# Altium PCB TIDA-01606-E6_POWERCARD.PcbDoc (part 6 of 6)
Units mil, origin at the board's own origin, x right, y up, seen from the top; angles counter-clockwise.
Board outline 13779.53 x 7874.02 mil, 4 copper layers (Top Layer, Gnd Layer, Pwr Layer, Bottom Layer), stack 94.4 mil thick; 550 components, 292 nets, 1594 pads, 572 vias.
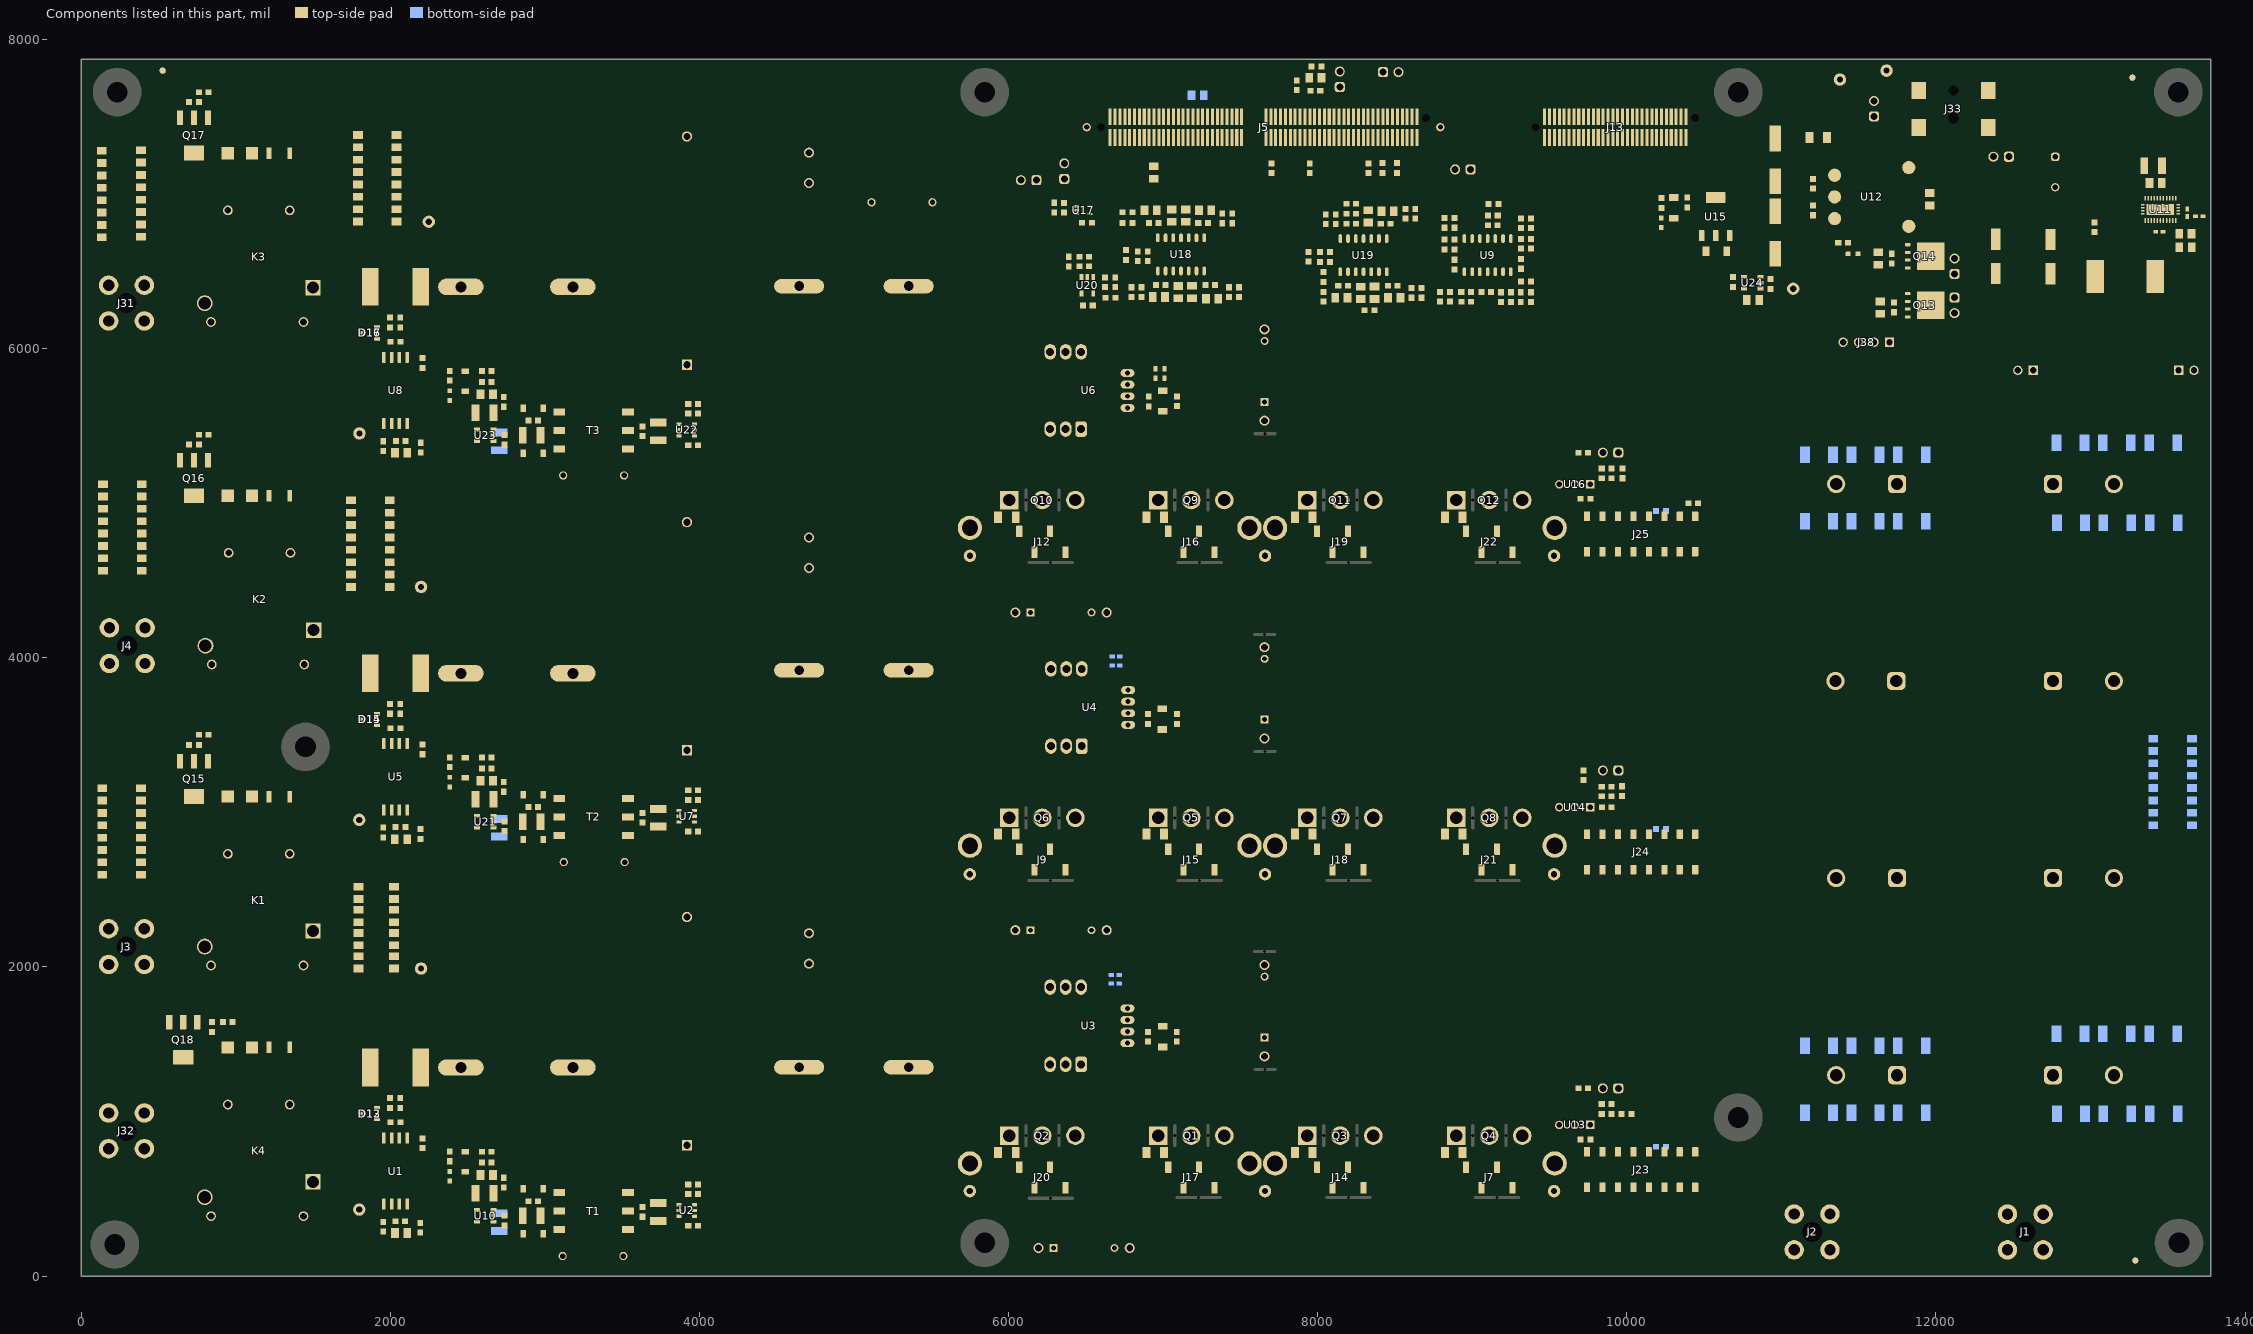
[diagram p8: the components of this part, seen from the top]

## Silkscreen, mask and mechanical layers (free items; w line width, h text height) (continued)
M4 3D STEP Bottom:
  lines w10: 6004.7,908.93 6004.7,2964.99 6004.7,5021.06 ; 6169.7,638.93 6219.7,688.93 6219.7,908.93 ; 6169.7,2694.99 6219.7,2744.99 6219.7,2964.99 ; 6169.7,4751.06 6219.7,4801.06 6219.7,5021.06 ; 6369.7,638.93 7033.48,638.93 ; 6369.7,2694.99 7033.48,2694.99 ; 6369.7,4751.06 7033.48,4751.06 ; 6434.7,908.93 6968.48,908.93 ; 6434.7,2964.99 6968.48,2964.99 ; 6434.7,5021.06 6968.48,5021.06 ; 7133.48,638.93 7183.48,688.93 7183.48,908.93 ; 7133.48,2694.99 7183.48,2744.99 7183.48,2964.99 ; 7133.48,4751.06 7183.48,4801.06 7183.48,5021.06 ; 7333.48,638.93 7997.26,638.93 ; 7333.48,2694.99 7997.26,2694.99 ; 7333.48,4751.06 7997.26,4751.06 ; 7398.48,908.93 7932.26,908.93 ; 7398.48,2964.99 7932.26,2964.99 ; 7398.48,5021.06 7932.26,5021.06 ; 8097.26,638.93 8147.26,688.93 8147.26,908.93 ; 8097.26,2694.99 8147.26,2744.99 8147.26,2964.99 ; 8097.26,4751.06 8147.26,4801.06 8147.26,5021.06 ; 8297.26,638.93 8961.04,638.93 ; 8297.26,2694.99 8961.04,2694.99 ; 8297.26,4751.06 8961.04,4751.06 ; 8362.26,908.93 8896.04,908.93 ; 8362.26,2964.99 8896.04,2964.99 ; 8362.26,5021.06 8896.04,5021.06 ; 9061.04,638.93 9111.04,688.93 9111.04,908.93 ; 9061.04,2694.99 9111.04,2744.99 9111.04,2964.99 ; 9061.04,4751.06 9111.04,4801.06 9111.04,5021.06 ; 9261.04,638.93 9742.93,638.93 ; 9261.04,2694.99 9742.93,2694.99 ; 9261.04,4751.06 9742.93,4751.06
  text ".Layer_Name" at -13.55,-858.49 h60
M5 Assembly Top:
  circle w10: c13573.69,5858.85 r7.25
  circle w10: c12623,5855.85 r7.25
  circle w10: c11701,6036.85 r7.25
  circle w10: c8421,7783.85 r7.25
  circle w10: c6181,7083.85 r7.25
  circle w10: c6548,6480.85 r7.25
  circle w10: c9742.93,4884.85 r7.25
  circle w10: c8960,4782.85 r7.25
  circle w10: c7999,4780.85 r7.25
  circle w10: c7035,4784.85 r7.25
  circle w10: c6071,4781.85 r7.25
  circle w10: c9742.93,2825.85 r7.25
  circle w10: c8964,2727.85 r7.25
  circle w10: c7998,2725.85 r7.25
  circle w10: c7036,2723.85 r7.25
  circle w10: c6071,2723.85 r7.25
  circle w10: c9742,768.85 r7.25
  circle w10: c8961,670.85 r7.25
  circle w10: c7997,669.85 r7.25
  circle w10: c7035,670.85 r7.25
  circle w10: c6071,665.85 r7.25
  circle w10: c1931,6063.85 r7.25
  circle w10: c1930,3565.29 r7.25
  circle w10: c1930,1014.6 r7.25
  circle w10: c6419,6922 r9.22
  circle w10: c6363,7098 r9.22
  circle w10: c8969,7187 r9.22
  circle w10: c10484,6815 r9.22
  circle w10: c11330,7113 r9.22
  circle w10: c12469,7240 r9.22
  circle w10: c12338,7669 r9.22
  circle w10: c9836,5332 r9.22
  circle w10: c6472,5498 r9.22
  circle w10: c6474,3445 r9.22
  circle w10: c9835,3271 r9.22
  circle w10: c6471,1388 r9.22
  circle w10: c9843,1217 r9.22
  circle w10: c8144,7689 r9.85
  circle w10: c2687,353 r7
  circle w10: c2689,2901.6 r7
  circle w10: c2688,5404 r7
  circle w10: c822,7420 r13.15
  circle w10: c816,5212 r7
  circle w10: c819,3264 r11.18
  circle w10: c750,1579 r10.05
  lines w10: -882.55,-930.17 5717.45,-930.17 ; -882.55,-726.83 5719.45,-726.83 ; -882.55,-523.5 -882.55,-1133.5 3122.45,-1133.5 5719.45,-1133.5 5719.45,-523.5 -882.05,-523.5 -882.05,-1133.5 693.45,-1133.5 ; 1582.45,-1133.5 1582.45,-523.5 ; 2849.45,-726.83 2849.45,-523.5 ; 3689.45,-726.83 3689.45,-523.5 ; 4311.45,-1140 4311.45,-937.17
  text "2" at 6643,7482 h72.83
  text "120" at 8631,7481 h72.83
  text "122" at 9421,7480 h72.83
  text "180" at 10368,7474 h72.83
  text "1" at 6642,7265 h72.83
  text "119" at 8630,7241 h72.83
  text "121" at 9411,7238 h72.83
  text "179" at 10372,7234 h72.83
  text "COMPONENTS MARKED 'DNP' SHOULD NOT BE POPULATED." at 562.95,-318.5 h25
  text "ASSEMBLY VARIANT:" at 562.45,-434 h25
  text ".VariantName" at 1598.45,-434 h25
  text "PCB VIEWED FROM TOP SIDE" at -819.05,-655.67 h25
  text "BOARD #:" at 1657.45,-655.67 h25
  text ".PRJ_Number" at 2202.95,-655.67 h25
  text "REV:" at 3047.45,-655.67 h25
  text ".PCB_Rev" at 3338.95,-655.67 h25
  text "SVN REV:" at 3885.45,-655.67 h25
  text ".VersionControl_RevNumber" at 4391.45,-655.67 h25
  text "LAYER NAME =" at -819.05,-858.49 h25
  text "'.Layer_Name'" at -471,-859 h25
  text "TID #:" at 1657.45,-859 h25
  text ".TID" at 2202.95,-859 h25
  text "PLOT NAME =" at -819.05,-1064.34 h25
  text ".plot_File_Name" at -13.55,-1064.34 h25
  text "GENERATED    :" at 1659.45,-1064.34 h25
  text ".Print_Date" at 2528.95,-1064.34 h25
  text ".Print_Time" at 3257.95,-1064.34 h25
  text "TEXAS INSTRUMENTS" at 4522.45,-1064.34 h25
M6 Assembly Bottom:
  circle w10: c1930,1090 r8.46
  circle w10: c1930,3639.4 r8.46
  circle w10: c1930,6140 r8.46
  circle w10: c6010,5060 r28.28
  circle w10: c6970,5069.84 r28.28
  circle w10: c7930,5069.84 r28.28
  circle w10: c8900,5069.84 r28.28
  circle w10: c6000,3010 r28.28
  circle w10: c6970,3010 r28.28
  circle w10: c7930,3000 r28.28
  circle w10: c8900,3020 r28.28
  circle w10: c8890,950.61 r28.28
  circle w10: c7940,960 r28.28
  circle w10: c6970,950 r28.28
  circle w10: c6010,950 r28.28
  circle w10: c9731,5123 r6.08
  circle w10: c9735,3028 r6.08
  circle w10: c9735,974 r6.08
  lines w10: -883.05,-727.33 5718.95,-727.33 ; -881.05,-930.67 5718.95,-930.67 ; 524.95,-1140.5 524.95,-937.67 ; 1146.95,-727.33 1146.95,-524 ; 1986.95,-727.33 1986.95,-524 ; 3253.95,-1134 3253.95,-524 ; 4142.95,-1134 5718.45,-1134 5718.45,-524 -883.05,-524 -883.05,-1134 1713.95,-1134 5718.95,-1134 5718.95,-524
  text "U14" at 9685,3023 h25
  text "COMPONENTS MARKED 'DNP' SHOULD NOT BE POPULATED." at 5511.45,-318 h25
  text ".VariantName" at 4467.45,-434 h25
  text "ASSEMBLY VARIANT:" at 5506.45,-434 h25
  text ".VersionControl_RevNumber" at 444.95,-656.17 h25
  text "SVN REV:" at 950.95,-656.17 h25
  text ".PCB_Rev" at 1497.45,-656.17 h25
  text "REV:" at 1788.95,-656.17 h25
  text ".PRJ_Number" at 2633.45,-656.17 h25
  text "BOARD #:" at 3178.95,-656.17 h25
  text "PCB VIEWED FROM BOTTOM SIDE" at 5655.45,-656.17 h25
  text "'.Layer_Name'" at 5339,-832 h30
  text "LAYER NAME =" at 5665.95,-832.49 h25
  text ".TID" at 2633.45,-859.5 h25
  text "TID #:" at 3178.95,-859.5 h25
  text "TEXAS INSTRUMENTS" at 313.95,-1064.84 h25
  text ".Print_Time" at 1578.45,-1064.84 h25
  text ".Print_Date" at 2307.45,-1064.84 h25
  text "GENERATED    :" at 3176.95,-1064.84 h25
  text ".plot_File_Name" at 4849.95,-1064.84 h25
  text "PLOT NAME =" at 5655.45,-1064.84 h25
M9 Title Sheet:
  drawing of 69 lines, arcs and shapes, not listed
  text "1" at 149.29,15036.5 h70
  text "2" at 2644.95,15036.5 h70
  text "3" at 5134.29,15036.5 h70
  text "4" at 7640.96,15036.5 h70
  text "5" at 16764.95,15036.5 h70
  text "6" at 19269.95,15036.5 h70
  text "A" at -1007.05,6893.5 h70
  text "A" at 20417.95,6893.5 h70
  text "B" at -1007.05,4513.5 h70
  text "B" at 20417.95,4513.5 h70
  text "C" at -1007.05,2138.5 h70
  text "C" at 20417.95,2138.5 h70
  text "PROJECT TITLE:" at 17377.95,277.5 h45
  text ".PRJ_Title" at 17427.95,144.17 h70
  text "DESIGNED FOR:" at 17377.95,-23.5 h45
  text ".PRJ_Customer" at 17427.95,-163.5 h70
  text "D" at -1007.05,-231.5 h70
  text "D" at 20417.95,-231.5 h70
  text "FILE NAME:" at 17377.95,-323.5 h45
  text ".PCB_File_Name_No_Path" at 17427.95,-443.5 h70
  text "Texas Instruments (TI) and/or its licensors do not warrant the accuracy or completeness of this specification" at 5783.45,-605.34 h45
  text "ENGINEER:" at 17377.95,-613.5 h45
  text "LAYOUT BY:" at 18882.95,-613.5 h45
  text "or any information contained therein. TI and/or its licensors do not warrant that this design will meet" at 5738.46,-718 h45
  text ".PRJ_Engineer" at 17427.95,-768.49 h70
  text ".PCB_Layout" at 18933.45,-768.49 h70
  text "the specifications, will be suitable for your application or fit for any particular purpose, or will operate in" at 5738.46,-830.67 h45
  text "ALTIUM DESIGNER VERSION:" at 18882.95,-923.5 h45
  text "an implementation. TI and/or its licensors do not warrant that the design is production worthy. You should" at 5738.46,-943.33 h45
  text "completely validate and test your design implementation to confirm the system functionality for your application." at 5783.45,-1056 h45
  text ".print_Scale" at 17427.95,-1056.83 h70
  text ".Application_BuildNumber" at 18933.45,-1056.83 h70
  text "1" at 149.29,-1263.5 h70
  text "2" at 2644.95,-1263.5 h70
  text "3" at 5134.29,-1263.5 h70
  text "4" at 7640.96,-1263.5 h70
  text "5" at 16764.95,-1263.5 h70
  text "6" at 19269.95,-1263.5 h70
M10 Fab Notes:
  drawing of 228 lines, arcs and shapes, not listed
  text "DESIGN INFORMATION" at 18417.37,6834.03 h60
  text "(REFER ALSO ARRAY/PANEL PROFILING INFORMATION)" at 18055.81,6672.32 h60
  text "BOARD SIZE" at 17369.81,6668.03 h60
  text "350MM" at 17832.13,6540.21 h60
  text "X" at 18337.81,6540.21 h60
  text "200MM" at 18569.13,6540.21 h60
  text "Number of Layers :" at 17772.81,6343.03 h60
  text "4" at 18867.62,6333.04 h60
  text "10" at 18846.45,6206 h60
  text "MIN. TRACK WIDTH:" at 17772.81,6204.03 h60
  text "MIL" at 19023.81,6204.03 h60
  text "MIL" at 19024.45,6087 h60
  text "7.87" at 18789,6079 h60
  text "MIN. CLEARANCE:" at 17772.81,6072.03 h60
  text "12" at 18856,5959 h60
  text "MIL" at 19027.45,5953 h60
  text "MIN. VIA DRILL SIZE:" at 17772.81,5940.03 h60
  text "MINIMUM ANNULAR RING" at 17443.58,5794.04 h60
  text "EXTERNAL" at 19175.81,5794.04 h60
  text "5.90 MIL" at 18487.45,5792 h60
  text "PER" at 17643.58,5676.04 h60
  text "IPC-D-275 CLASS 2 LEVEL C" at 17863.58,5676.03 h60
  text "MIL, HOLES" at 19351.81,5563.75 h60
  text "+/-" at 18959.35,5563.04 h60
  text "+/-" at 19813.35,5563.04 h60
  text "REGISTRATION TOLERANCES:" at 17443.58,5558.03 h60
  text "METAL" at 18643.35,5558.03 h60
  text "5" at 19219.55,5558.04 h60
  text "3" at 20052.55,5558.04 h60
  text "MIL" at 20168.81,5558.03 h60
  text "MATERIAL:" at 17368.81,5348.58 h60
  text "FR-4 High Tg" at 18355.25,5208.24 h60
  text "FR-408" at 17789.81,5199.67 h60
  text "X" at 18196.35,5200.03 h60
  text "OTHER" at 19277.81,5199.67 h60
  text "OTHER" at 19509.81,5039.67 h60
  text "94.48 MIL (2.4mm) +/-10%" at 18109.91,5036.96 h60
  text "THICKNESS:" at 17443.58,5032.67 h60
  text "X" at 17981.75,5032.67 h60
  text "TOLERANCE:" at 17443.58,4874.67 h60
  text "X" at 18282.88,4874.67 h60
  text "ANSI IPC-6012 TYPE 3 CLASS 2" at 18469.82,4874.67 h60
  text "OTHER +/-" at 18469.81,4718.67 h60
  text "BOW & TWIST:" at 17443.58,4561.67 h60
  text "X" at 18282.88,4561.67 h60
  text "ANSI IPC-6012 TYPE 3 CLASS 2" at 18469.82,4561.67 h60
  text "OTHER +/-" at 18469.81,4403.17 h60
  text "COPPER THICKNESS (FINISHED):" at 17368.81,4267.67 h60
  text "X" at 19618.35,4119.03 h60
  text "1.4MIL (1oz)" at 18248.81,4114.96 h60
  text "2MIL (1.4oz)" at 19015.81,4114.96 h60
  text "2.8MIL (2oz)" at 19742.81,4114.96 h60
  text "OUTER:" at 17725.81,4110.67 h60
  text "1.4MIL (1oz)" at 18248.81,3957.96 h60
  text "2.8MIL (2oz)" at 19015.81,3957.96 h60
  text "N/A" at 19742.35,3958.32 h60
  text "X" at 18888.35,3956.03 h60
  text "INNER SIGNAL:" at 17436.73,3953.67 h60
  text "DRILLING:" at 17368.81,3814.67 h60
  text "REFERENCE:" at 17443.58,3697.67 h60
  text "X" at 18091.81,3697.67 h60
  text "AS SHOWN" at 18278.81,3697.67 h60
  text "X" at 18992.81,3697.67 h60
  text "NC_DRILL FILES" at 19129.81,3697.67 h60
  text "PTH MIN COPPER THICKNESS:" at 17443.58,3539.67 h60
  text "X" at 18793.81,3539.67 h60
  text "1MIL" at 18930.81,3539.67 h60
  text "OTHER" at 19427.81,3539.67 h60
  text "BOARD FINISH:" at 17368.81,3380.67 h60
  text "SILKSCREEN:" at 17524.03,3262.67 h60
  text "X" at 18472.81,3262.67 h60
  text "TOP" at 18598.81,3262.67 h60
  text "BOTTOM" at 19109.81,3262.67 h60
  text "X" at 18990.35,3259.03 h60
  text "SILKSCREEN COLOR:" at 17524.03,3095.67 h60
  text "X" at 18471.77,3095.67 h60
  text "WHITE" at 18598.81,3095.67 h60
  text "OTHER" at 19109.81,3095.67 h60
  text "SOLDER RESIST COLOR:" at 17524.03,2925.67 h60
  text "X" at 18091.77,2766.48 h60
  text "GREEN" at 18218.81,2766.48 h60
  text "BLUE" at 18809.81,2766.48 h60
  text "OTHER" at 19347.81,2766.48 h60
  text "IMMERSION GOLD (ENIG)" at 18429.81,2577.96 h60
  text "ENEPIG" at 19767.35,2574.67 h60
  text "SURFACE FINISH:" at 17368.81,2573.67 h60
  text "X" at 18242.86,2573.67 h60
  text "IMM. TIN/SILVER OR EQUIV" at 17698.35,2416.67 h60
  text "OTHER" at 19129.81,2416.67 h60
  text "ARRAY/PANEL:" at 17368.81,2237.67 h60
  text "CUT AND TRIM PER MECH LAYER 1" at 18429.81,2233.39 h60
  text "X" at 19097.35,2083.03 h60
  text "N.C. ROUTE" at 18429.81,2081.67 h60
  text "V. SCORE" at 19295.81,2081.67 h60
  text "CERTIFICATION:" at 17368.81,1944.67 h60
  text "MATERIALS AND WORKMANSHIP FOR ALL PCBS" at 18093.81,1944.67 h60
  text "TO MEET OR EXCEED THE REQUIREMENTS OF:" at 18093.81,1846.67 h60
  text "X" at 17720.31,1710.17 h60
  text "ANSI IPC-A-600F CLASS ->" at 17859.31,1710.17 h60
  text "X" at 19498.37,1710.17 h60
  text "2" at 19617.31,1710.17 h60
  text "1" at 19302.31,1708.67 h60
  text "3" at 19971.31,1708.67 h60
  text "X" at 17722.37,1550.67 h60
  text "UL 94V-0" at 17859.31,1550.67 h60
  text "X" at 18534.37,1550.67 h60
  text "RoHS" at 18671.31,1550.67 h60
  text "OTHER" at 19315.71,1550.67 h60
  text "PER ORDER" at 19712.77,1550.67 h60
  text "VIA TENTING:" at 18586.35,1417.03 h60
  text "ADDITIONAL REQUIREMENTS:" at 17368.81,1409.67 h60
  text "X" at 19672.34,1409 h60
  text "YES" at 19136.02,1407.95 h60
  text "NO" at 19500.82,1402.73 h60
  text "MICROSECTION:" at 17443.58,1294.67 h60
  text "YES" at 18349.31,1294.67 h60
  text "IMPEDANCE CONTROL:" at 18608.35,1288.03 h60
  text "YES" at 19592.35,1287.03 h60
  text "X" at 20131.45,1274 h60
  text "NO" at 19967.82,1269.73 h60
  text "REQUIRED" at 19210.81,1138.53 h60
  text "BARE BOARD ELEC. TEST:" at 17443.58,1135.67 h60
  text "NONE" at 18749.31,1135.67 h60
  text "X" at 19083.81,1135.67 h60
  text "PER ORDER" at 19802.81,1135.67 h60
  text "MANUFACTURER'S UL:" at 17443.58,978.67 h60
  text "RAIL" at 18609.31,974.39 h60
  text "METAL" at 19101.12,974.39 h60
  text "X" at 19476.35,974.03 h60
  text "SILK" at 19612.81,974.39 h60
M11 Gerber Information:
  lines w10: -882.55,-930.17 5717.45,-930.17 ; -882.55,-726.83 5719.45,-726.83 ; -882.55,-523.5 -882.55,-1133.5 3122.45,-1133.5 5719.45,-1133.5 5719.45,-523.5 -882.05,-523.5 -882.05,-1133.5 693.45,-1133.5 ; 1582.45,-1133.5 1582.45,-523.5 ; 2849.45,-726.83 2849.45,-523.5 ; 3689.45,-726.83 3689.45,-523.5 ; 4311.45,-1140 4311.45,-937.17
  text "ALL ARTWORK VIEWED FROM TOP SIDE" at -819.05,-655.67 h60
  text "BOARD #:" at 1657.45,-655.67 h60
  text ".PRJ_Number" at 2202.95,-655.67 h30
  text "REV:" at 3047.45,-655.67 h60
  text ".PCB_Rev" at 3338.95,-655.67 h60
  text "SVN REV:" at 3885.45,-655.67 h60
  text ".VersionControl_RevNumber" at 4391.45,-655.67 h60
  text "TID #:" at 1657.45,-859 h60
  text ".TID" at 2202.95,-859 h60
  text "LAYER NAME =" at -850.05,-860.49 h60
  text "PLOT NAME =" at -819.05,-1064.34 h60
  text ".plot_File_Name" at -13.55,-1064.34 h30
  text "GENERATED    :" at 1659.45,-1064.34 h60
  text ".Print_Date" at 2528.95,-1064.34 h60
  text ".Print_Time" at 3257.95,-1064.34 h60
  text "TEXAS INSTRUMENTS" at 4522.45,-1064.34 h60
M12 Stackup:
  drawing of 295 lines, arcs and shapes, not listed
  text "Layer" at 15677.5,8464.5 h60
  text "Name" at 16087.41,8464.5 h60
  text "Material" at 17017.16,8464.5 h60
  text "Thickness" at 17876.92,8464.5 h60
  text "Constant" at 18526.76,8464.5 h60
  text "Board Layer Stack" at 19096.62,8464.5 h60
  text "Top Overlay" at 16087.41,8344.5 h60
  text "Top Solder" at 16087.41,8224.5 h60
  text "Solder Resist" at 17017.16,8224.5 h60
  text "0.40mil" at 17876.92,8224.5 h60
  text "3.5" at 18526.76,8224.5 h60
  text "1" at 15677.5,8104.5 h60
  text "Top Layer" at 16087.41,8104.5 h60
  text "2.80mil" at 17876.92,8104.5 h60
  text "Dielectric 1" at 16087.41,7984.5 h60
  text "FR-4-High Tg" at 17017.16,7984.5 h60
  text "12.00mil" at 17876.92,7984.5 h60
  text "4.2" at 18526.76,7984.5 h60
  text "2" at 15677.5,7864.5 h60
  text "Gnd Layer" at 16087.41,7864.5 h60
  text "2.80mil" at 17876.92,7864.5 h60
  text "Dielectric2" at 16087.41,7744.5 h60
  text "FR-4-High Tg" at 17017.16,7744.5 h60
  text "59.20mil" at 17876.92,7744.5 h60
  text "4.2" at 18526.76,7744.5 h60
  text "3" at 15677.5,7624.5 h60
  text "Pwr Layer" at 16087.41,7624.5 h60
  text "2.80mil" at 17876.92,7624.5 h60
  text "Dielectric 3" at 16087.41,7504.5 h60
  text "FR-4-High Tg" at 17017.16,7504.5 h60
  text "12.00mil" at 17876.92,7504.5 h60
  text "4.2" at 18526.76,7504.5 h60
  text "4" at 15677.5,7384.5 h60
  text "Bottom Layer" at 16087.41,7384.5 h60
  text "2.80mil" at 17876.92,7384.5 h60
  text "Bottom Solder" at 16087.41,7264.5 h60
  text "Solder Resist" at 17017.16,7264.5 h60
  text "0.40mil" at 17876.92,7264.5 h60
  text "3.5" at 18526.76,7264.5 h60
  text "Bottom Overlay" at 16087.41,7144.5 h60
M13 Component Bodies Top:
  text ".Layer_Name" at -13.55,-858.49 h60
M14 Component Bodies Bottom:
  text ".Layer_Name" at -13.55,-858.49 h60
M15 Courtyards Top:
  text ".Layer_Name" at -13.55,-858.49 h60
M16 Courtyards Bottom:
  text ".Layer_Name" at -13.55,-858.49 h60
Drill Drawing:
  circle w10: c13480.74,13642.33 r33.33
  circle w10: c13480.74,10492.33 r20
  circle w10: c13480.74,10492.33 r33.33
  lines w10: 13447.41,9709 13514.08,9709 13514.08,9775.67 13447.41,9775.67 13447.41,9709 ; 13447.41,10759 13447.41,10775.67 13464.08,10792.33 13447.41,10809 13447.41,10825.67 13464.08,10825.67 13480.74,10809 13497.41,10825.67 13514.08,10825.67 13514.08,10809 13497.41,10792.33 13514.08,10775.67 13514.08,10759 13497.41,10759 13480.74,10775.67 13464.08,10759 13447.41,10759 ; 13447.41,11509 13480.74,11525.67 13514.08,11509 13497.41,11542.33 13514.08,11575.67 13480.74,11559 13447.41,11575.67 13464.08,11542.33 13447.41,11509 ; 13447.41,11725.67 13514.08,11725.67 13480.74,11659 13447.41,11725.67 ; 13447.41,11959 13514.08,11959 13514.08,12025.67 13447.41,12025.67 13447.41,11959 ; 13447.41,12425.67 13464.08,12425.67 13480.74,12409 13497.41,12425.67 13514.08,12425.67 13497.41,12442.33 13514.08,12459 13497.41,12459 13480.74,12475.67 13464.08,12459 13447.41,12459 13464.08,12442.33 13447.41,12425.67 ; 13447.41,12592.33 13480.74,12559 13514.08,12592.33 13480.74,12625.67 13447.41,12592.33 ; 13447.41,12775.67 13514.08,12775.67 13480.74,12709 13447.41,12775.67 ; 13447.41,13175.67 13464.08,13175.67 13464.08,13159 13497.41,13159 13497.41,13175.67 13514.08,13175.67 13514.08,13209 13497.41,13209 13497.41,13225.67 13464.08,13225.67 13464.08,13209 13447.41,13209 13447.41,13175.67 ; 13447.41,13759 13480.74,13775.67 13514.08,13759 13497.41,13792.33 13514.08,13825.67 13480.74,13809 13447.41,13825.67 13464.08,13792.33 13447.41,13759 ; 13447.41,14059 13447.41,14075.67 13464.08,14092.33 13447.41,14109 13447.41,14125.67 13464.08,14125.67 13480.74,14109 13497.41,14125.67 13514.08,14125.67 13514.08,14109 13497.41,14092.33 13514.08,14075.67 13514.08,14059 13497.41,14059 13480.74,14075.67 13464.08,14059 13447.41,14059 ; 13460.74,11522.33 13480.74,11532.33 13500.74,11522.33 13490.74,11542.33 13500.74,11562.33 13480.74,11552.33 13460.74,11562.33 13470.74,11542.33 13460.74,11522.33 ; 13460.74,11972.33 13500.74,11972.33 13500.74,12012.33 13460.74,12012.33 13460.74,11972.33 ; 13460.74,12762.33 13500.74,12762.33 13480.74,12722.33 13460.74,12762.33 ; 13460.74,14072.33 13460.74,14082.33 13470.74,14092.33 13460.74,14102.33 13460.74,14112.33 13470.74,14112.33 13480.74,14102.33 13490.74,14112.33 13500.74,14112.33 13500.74,14102.33 13490.74,14092.33 13500.74,14082.33 13500.74,14072.33 13490.74,14072.33 13480.74,14082.33 13470.74,14072.33 13460.74,14072.33
  lines w15: 13387.62,9364 17398.54,9364 ; 13387.62,14164 17398.54,14164 ; 13938.5,9214 13938.5,14314 ; 14538.34,9214 14538.34,14314 ; 15688,9214 15688,14314 ; 16193.88,9214 16193.88,14314 ; 13387.62,9214 17398.54,9214 17398.54,14314 13387.62,14314 13387.62,9214
  text "Symbol" at 13477.62,14209 h72
  text "Count" at 13983.5,14209 h72
  text "Hole Size" at 14583.34,14209 h72
  text "Plated" at 15733,14209 h72
  text "Hole Length" at 16238.88,14209 h72
  text "1" at 13983.5,14059 h60
  text "62.99mil (1.600mm)" at 14583.34,14059 h60
  text "NPTH" at 15733,14059 h60
  text "-" at 16238.88,14059 h60
  text "1" at 13983.5,13909 h60
  text "70.87mil (1.800mm)" at 14583.34,13909 h60
  text "NPTH" at 15733,13909 h60
  text "-" at 16238.88,13909 h60
  text "A" at 13448.53,13899.01 h66.67
  text "2" at 13983.5,13759 h60
  text "33.07mil (0.840mm)" at 14583.34,13759 h60
  text "PTH" at 15733,13759 h60
  text "-" at 16238.88,13759 h60
  text "2" at 13983.5,13609 h60
  text "33.47mil (0.850mm)" at 14583.34,13609 h60
  text "PTH" at 15733,13609 h60
  text "-" at 16238.88,13609 h60
  text "4" at 13983.5,13459 h60
  text "40.16mil (1.020mm)" at 14583.34,13459 h60
  text "PTH" at 15733,13459 h60
  text "-" at 16238.88,13459 h60
  text "W" at 13448.53,13449.01 h66.67
  text "4" at 13983.5,13309 h60
  text "40.95mil (1.040mm)" at 14583.34,13309 h60
  text "PTH" at 15733,13309 h60
  text "-" at 16238.88,13309 h60
  text "F" at 13448.53,13299.01 h66.67
  text "4" at 13983.5,13159 h60
  text "50.00mil (1.270mm)" at 14583.34,13159 h60
  text "NPTH" at 15733,13159 h60
  text "-" at 16238.88,13159 h60
  text "4" at 13983.5,13009 h60
  text "77.95mil (1.980mm)" at 14583.34,13009 h60
  text "PTH" at 15733,13009 h60
  text "-" at 16238.88,13009 h60
  text "J" at 13448.53,12999.01 h66.67
  text "4" at 13983.5,12859 h60
  text "81.10mil (2.060mm)" at 14583.34,12859 h60
  text "PTH" at 15733,12859 h60
  text "-" at 16238.88,12859 h60
  text "I" at 13459.64,12849.01 h66.67
  text "6" at 13983.5,12709 h60
  text "47.24mil (1.200mm)" at 14583.34,12709 h60
  text "PTH" at 15733,12709 h60
  text "-" at 16238.88,12709 h60
  text "6" at 13983.5,12559 h60
  text "62.99mil (1.600mm)" at 14583.34,12559 h60
  text "PTH" at 15733,12559 h60
  text "216.54mil (5.500mm)" at 16238.88,12559 h60
  text "6" at 13983.5,12409 h60
  text "70.87mil (1.800mm)" at 14583.34,12409 h60
  text "PTH" at 15733,12409 h60
  text "196.85mil (5.000mm)" at 16238.88,12409 h60
  text "\" at 13448.53,12260.12 h66.67
  text "6" at 13983.5,12259 h60
  text "129.92mil (3.300mm)" at 14583.34,12259 h60
  text "NPTH" at 15733,12259 h60
  text "-" at 16238.88,12259 h60
  text "8" at 13983.5,12109 h60
  text "42.91mil (1.090mm)" at 14583.34,12109 h60
  text "PTH" at 15733,12109 h60
  text "-" at 16238.88,12109 h60
  text "H" at 13448.53,12099.01 h66.67
  text "9" at 13983.5,11959 h60
  text "133.86mil (3.400mm)" at 14583.34,11959 h60
  text "PTH" at 15733,11959 h60
  text "-" at 16238.88,11959 h60
  text "10" at 13983.5,11809 h60
  text "7.87mil (0.200mm)" at 14583.34,11809 h60
  text "PTH" at 15733,11809 h60
  text "-" at 16238.88,11809 h60
  text "D" at 13448.53,11799.01 h66.67
  text "12" at 13983.5,11659 h60
  text "20.00mil (0.508mm)" at 14583.34,11659 h60
  text "NPTH" at 15733,11659 h60
  text "300.00mil (7.620mm)" at 16238.88,11659 h60
  text "12" at 13983.5,11509 h60
  text "43.31mil (1.100mm)" at 14583.34,11509 h60
  text "PTH" at 15733,11509 h60
  text "-" at 16238.88,11509 h60
  text "12" at 13983.5,11359 h60
  text "105.12mil (2.670mm)" at 14583.34,11359 h60
  text "PTH" at 15733,11359 h60
  text "-" at 16238.88,11359 h60
  text "E" at 13448.53,11349.01 h66.67
  text "14" at 13983.5,11209 h60
  text "43.31mil (1.100mm)" at 14583.34,11209 h60
  text "PTH" at 15733,11209 h60
  text "-" at 16238.88,11209 h60
  text "U" at 13448.53,11199.01 h66.67
  text "16" at 13983.5,11059 h60
  text "78.74mil (2.000mm)" at 14583.34,11059 h60
  text "PTH" at 15733,11059 h60
  text "-" at 16238.88,11059 h60
  text "K" at 13448.53,11049.01 h66.67
  text "17" at 13983.5,10909 h60
  text "35.43mil (0.900mm)" at 14583.34,10909 h60
  text "PTH" at 15733,10909 h60
  text "-" at 16238.88,10909 h60
  text "N" at 13448.53,10899.01 h66.67
  text "18" at 13983.5,10759 h60
  text "40.00mil (1.016mm)" at 14583.34,10759 h60
  text "PTH" at 15733,10759 h60
  text "-" at 16238.88,10759 h60
  text "18" at 13983.5,10609 h60
  text "51.18mil (1.300mm)" at 14583.34,10609 h60
  text "PTH" at 15733,10609 h60
  text "-" at 16238.88,10609 h60
  text "G" at 13448.53,10599.01 h66.67
  text "24" at 13983.5,10459 h60
  text "31.50mil (0.800mm)" at 14583.34,10459 h60
  text "PTH" at 15733,10459 h60
  text "-" at 16238.88,10459 h60
  text "24" at 13983.5,10309 h60
  text "45.28mil (1.150mm)" at 14583.34,10309 h60
  text "PTH" at 15733,10309 h60
  text "-" at 16238.88,10309 h60
  text "C" at 13448.53,10299.01 h66.67
  text "24" at 13983.5,10159 h60
  text "72.84mil (1.850mm)" at 14583.34,10159 h60
  text "PTH" at 15733,10159 h60
  text "-" at 16238.88,10159 h60
  text "]" at 13459.64,10149.01 h66.67
  text "29" at 13983.5,10009 h60
  text "20.00mil (0.508mm)" at 14583.34,10009 h60
  text "NPTH" at 15733,10009 h60
  text "150.00mil (3.810mm)" at 16238.88,10009 h60
  text "B" at 13448.53,9999.01 h66.67
  text "36" at 13983.5,9859 h60
  text "80.00mil (2.032mm)" at 14583.34,9859 h60
  text "PTH" at 15733,9859 h60
  text "-" at 16238.88,9859 h60
  text "L" at 13448.53,9849.01 h66.67
  text "86" at 13983.5,9709 h60
  text "28.00mil (0.711mm)" at 14583.34,9709 h60
  text "PTH" at 15733,9709 h60
  text "-" at 16238.88,9709 h60
  text "_" at 13448.53,9582.33 h66.67
  text "140" at 13983.5,9559 h60
  text "12.00mil (0.305mm)" at 14583.34,9559 h60
  text "PTH" at 15733,9559 h60
  text "-" at 16238.88,9559 h60
  text "^" at 13448.53,9421.23 h66.67
  text "336" at 13983.5,9409 h60
  text "16.00mil (0.406mm)" at 14583.34,9409 h60
  text "PTH" at 15733,9409 h60
  text "-" at 16238.88,9409 h60
  text "895 Total" at 13983.5,9259 h60
  text "Slot definitions :" at 13477.62,9114.03 h60
  text "Routed Path Length" at 14510.31,9114.03 h60
  text "= Calculated from tool start centre position to tool end centre position." at 15612.98,9114.03 h60
  text "Hole Length" at 14510.31,9014.05 h60
  text "= Routed Path Length + Tool Size = Slot length as defined in the PCB layout" at 15203.11,9014.05 h60
  text "FOR 12MIL DRILL +0/-12MIL" at -323,8882 h60
  text "FOR 16MIL DRILL +0/-16MIL" at -324,8782 h60
  text "FOR PTH DRILL +/-3MIL" at -325,8685 h60
  text "FOR NPTH DRILL +/-2MIL" at -325,8592 h60
  text ".Layer_Name" at -13.55,-858.49 h60
M17 Embedded Cavity:
  text ".Layer_Name" at -13.55,-858.49 h60
M18 Embedded Assembly:
  text ".Layer_Name" at -13.55,-858.49 h60
M19 Embedded Keepout:
  circle w10: c9111.04,1695.15 r78.74
  circle w10: c8147.26,1695.15 r78.74
  circle w10: c7183.48,1695.15 r78.74
  circle w10: c9111.04,3751.21 r78.74
  circle w10: c8147.26,3751.21 r78.74
  circle w10: c9111.04,5807.28 r78.74
  circle w10: c8147.26,5807.28 r78.74
  circle w10: c7183.48,5807.28 r78.74
  circle w10: c7183.48,3751.21 r78.74
  circle w10: c6219.7,1695.15 r78.74
  circle w10: c6219.7,3751.21 r78.74
  circle w10: c6219.7,5807.28 r78.74
  circle w10: c5842.53,215 r168.56
  circle w10: c10722.53,1026 r168.56
  circle w10: c10722.53,7660 r168.56
  circle w10: c5846.53,7660 r168.56
  lines w10: 6163.48,1638.93 6219.7,1695.15 ; 6163.48,3694.99 6219.7,3751.21 ; 6163.48,5751.06 6219.7,5807.28 ; 6163.92,1750.93 6219.7,1695.15 ; 6163.92,3806.99 6219.7,3751.21 ; 6163.92,5863.06 6219.7,5807.28 ; 6219.7,908.93 6219.7,1695.15 ; 6219.7,2964.99 6219.7,3751.21 ; 6219.7,5021.06 6219.7,5807.28 ; 6271.7,1643.15 6219.7,1695.15 ; 6271.7,3699.21 6219.7,3751.21 ; 6271.7,5755.28 6219.7,5807.28 ; 6275.7,1751.15 6219.7,1695.15 ; 6275.7,3807.21 6219.7,3751.21 ; 6275.7,5863.28 6219.7,5807.28 ; 7127.26,1638.93 7183.48,1695.15 ; 7127.26,3694.99 7183.48,3751.21 ; 7127.26,5751.06 7183.48,5807.28 ; 7127.7,1750.93 7183.48,1695.15 ; 7127.7,3806.99 7183.48,3751.21 ; 7127.7,5863.06 7183.48,5807.28 ; 7183.48,908.93 7183.48,1695.15 ; 7183.48,2964.99 7183.48,3751.21 ; 7183.48,5021.06 7183.48,5807.28 ; 7235.48,1643.15 7183.48,1695.15 ; 7235.48,3699.21 7183.48,3751.21 ; 7235.48,5755.28 7183.48,5807.28 ; 7239.48,1751.15 7183.48,1695.15 ; 7239.48,3807.21 7183.48,3751.21 ; 7239.48,5863.28 7183.48,5807.28 ; 8091.04,1638.93 8147.26,1695.15 ; 8091.04,3694.99 8147.26,3751.21 ; 8091.04,5751.06 8147.26,5807.28 ; 8091.48,1750.93 8147.26,1695.15 ; 8091.48,3806.99 8147.26,3751.21 ; 8091.48,5863.06 8147.26,5807.28 ; 8147.26,908.93 8147.26,1695.15 ; 8147.26,2964.99 8147.26,3751.21 ; 8147.26,5021.06 8147.26,5807.28 ; 8199.26,1643.15 8147.26,1695.15 ; 8199.26,3699.21 8147.26,3751.21 ; 8199.26,5755.28 8147.26,5807.28 ; 8203.26,1751.15 8147.26,1695.15 ; 8203.26,3807.21 8147.26,3751.21 ; 8203.26,5863.28 8147.26,5807.28 ; 9054.82,1638.93 9111.04,1695.15 ; 9054.82,3694.99 9111.04,3751.21 ; 9054.82,5751.06 9111.04,5807.28 ; 9055.26,1750.93 9111.04,1695.15 ; 9055.26,3806.99 9111.04,3751.21 ; 9055.26,5863.06 9111.04,5807.28 ; 9111.04,908.93 9111.04,1695.15 ; 9111.04,2964.99 9111.04,3751.21 ; 9111.04,5021.06 9111.04,5807.28 ; 9163.04,1643.15 9111.04,1695.15 ; 9163.04,3699.21 9111.04,3751.21 ; 9163.04,5755.28 9111.04,5807.28 ; 9167.04,1751.15 9111.04,1695.15 ; 9167.04,3807.21 9111.04,3751.21 ; 9167.04,5863.28 9111.04,5807.28 ; 2306.06,641.34 2306.06,2058.66 3132.83,2058.66 3132.83,641.34 2306.06,641.34 ; 2306.06,3191.34 2306.06,4608.66 3132.83,4608.66 3132.83,3191.34 2306.06,3191.34 ; 2306.06,5691.34 3132.83,5691.34 3132.83,7108.66 2306.06,7108.66 2306.06,5691.34 ; 3200.18,150.22 3200.18,2551.79 5601.75,2551.79 5601.75,150.22 3200.18,150.22 ; 3200.18,2700.22 3200.18,5101.79 5601.75,5101.79 5601.75,2700.22 3200.18,2700.22 ; 3200.18,5200.22 5601.75,5200.22 5601.75,7601.79 3200.18,7601.79 3200.18,5200.22
  lines w30: 5629.92,0 11141.73,0 11141.73,7874.02 5629.92,7874.02 5629.92,0
  text ".Layer_Name" at -13.55,-858.49 h60

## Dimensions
5629.92,7874.02 to 0,7874.02 on M16 Courtyards Bottom
5629.92,7874.02 to 11141.73,7874.02 on M16 Courtyards Bottom
6219.7,3751.21 to 5629.92,0 on M16 Courtyards Bottom
3200.18,7601.79 to 5601.75,7601.79 on M16 Courtyards Bottom
2306.06,7108.66 to 3132.83,7108.66 on M16 Courtyards Bottom
2306.06,7108.66 to 2306.06,5691.34 on M16 Courtyards Bottom
3200.18,7601.79 to 3200.18,5200.22 on M16 Courtyards Bottom
6219.7,3751.21 to 6219.7,1695.15 on M16 Courtyards Bottom
6219.7,5807.28 to 6219.7,3751.21 on M16 Courtyards Bottom
-590.55,-400 to 409.45,-400 on M2 Board Dimensions
0,0 to 13779.53,0 on M2 Board Dimensions
0,0 to 0,7874.02 on M2 Board Dimensions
